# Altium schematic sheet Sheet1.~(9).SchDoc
size A3
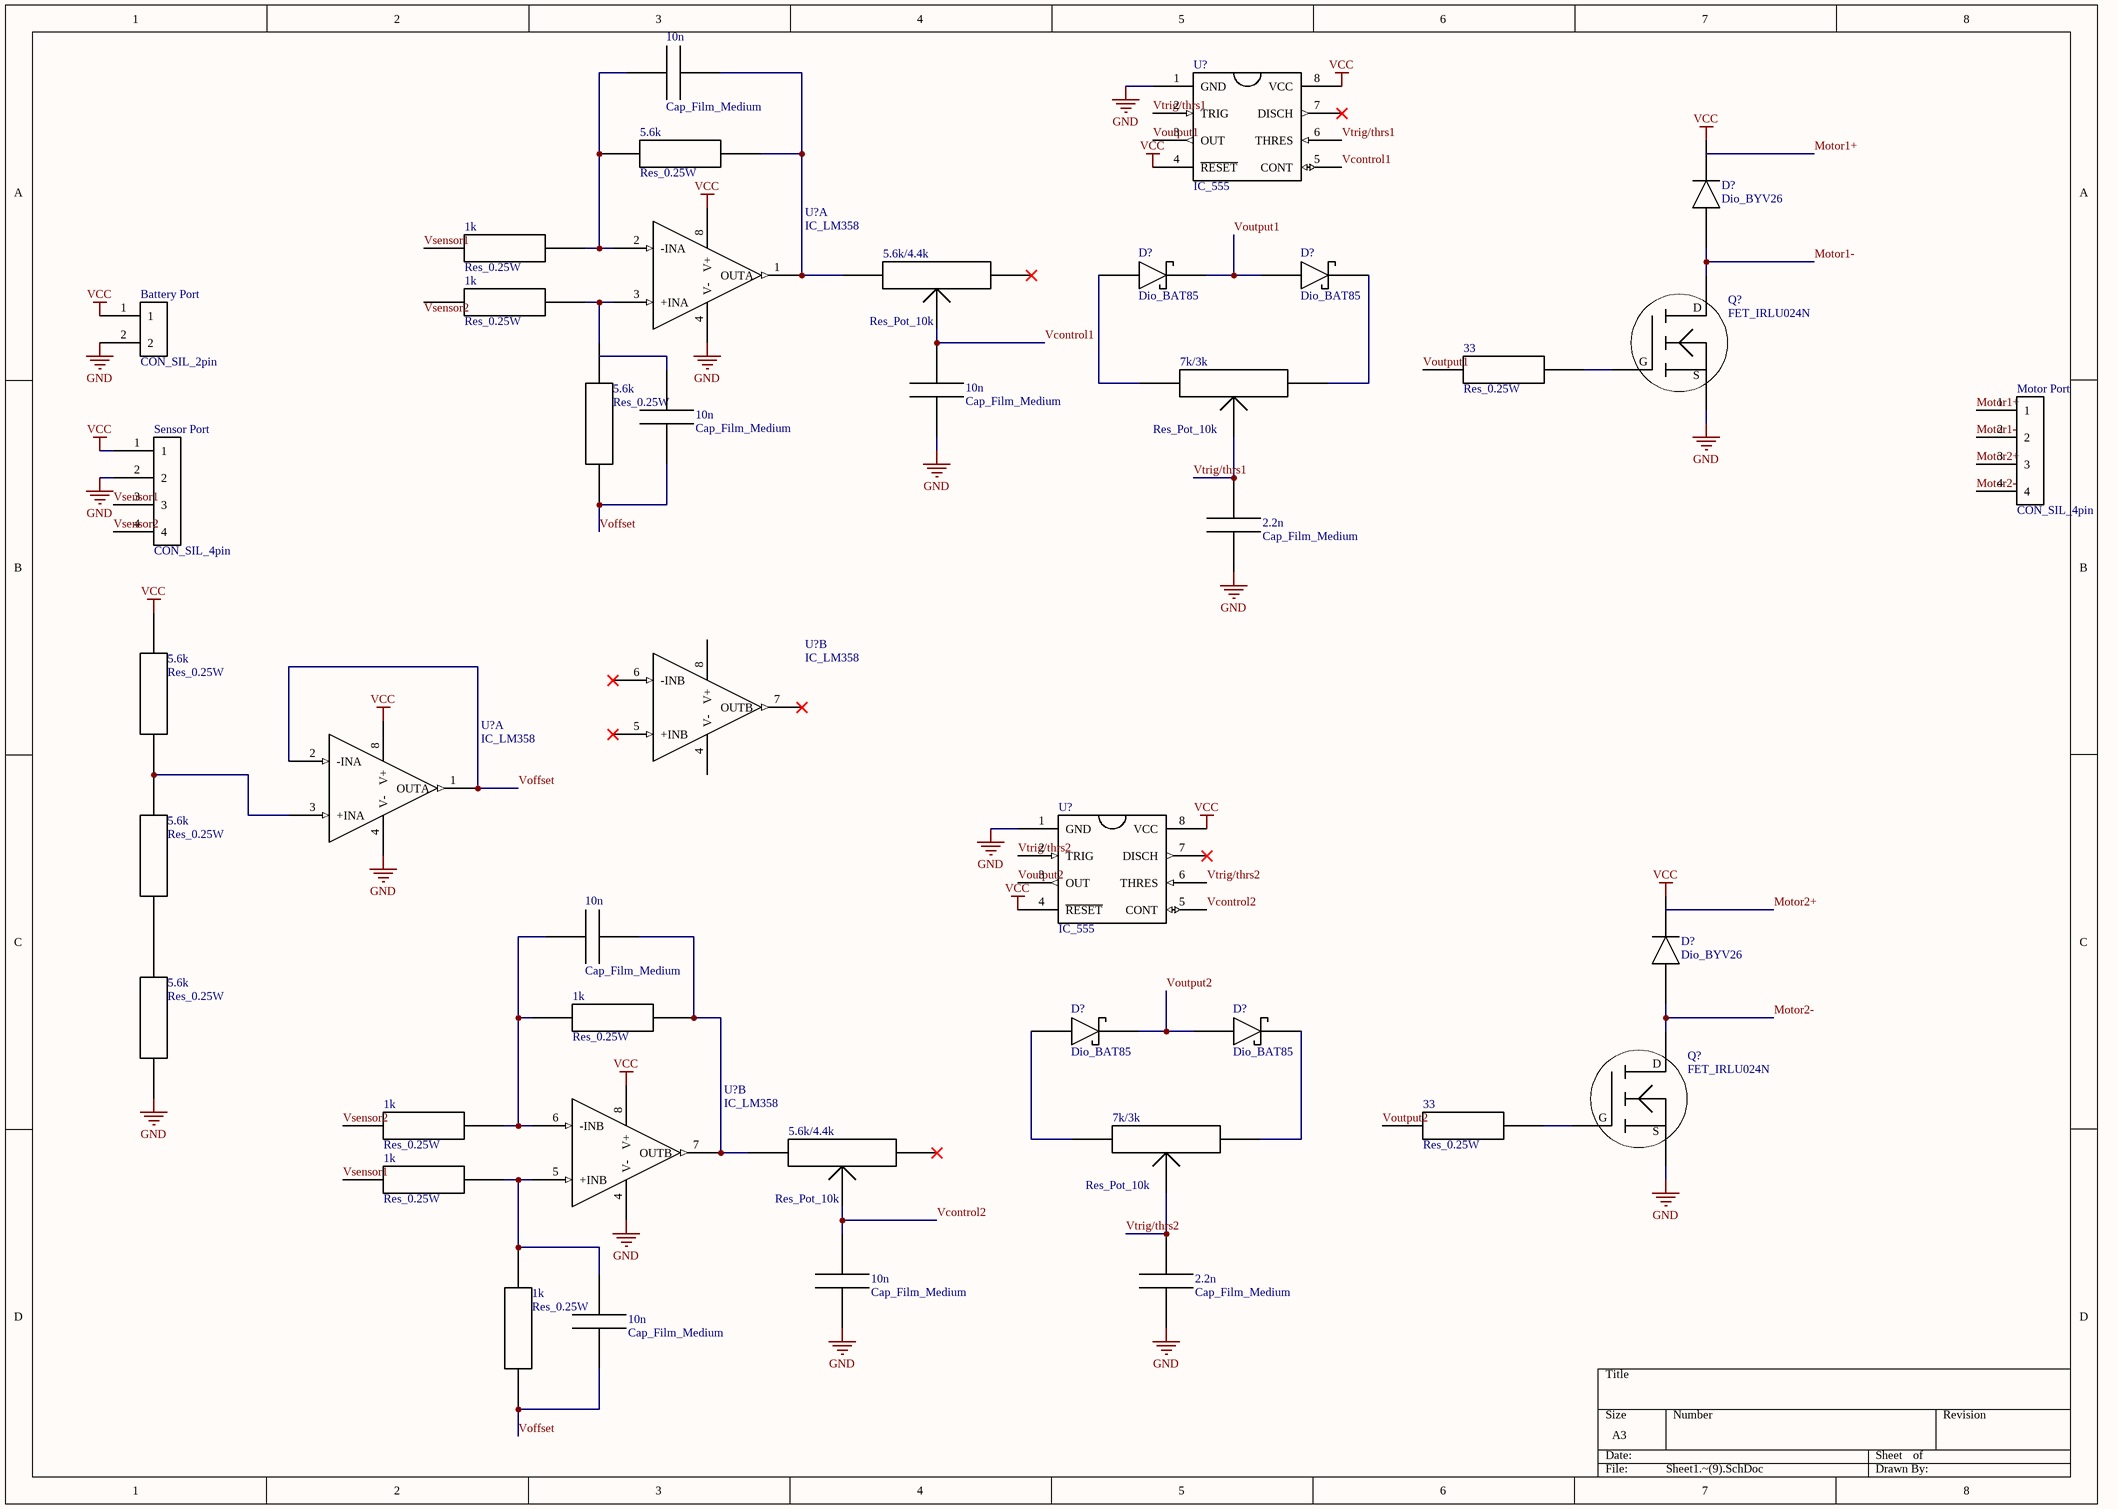
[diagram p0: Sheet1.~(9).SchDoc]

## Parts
(Parts that share a designator on the sheet are numbered #1, #2 ... from top to bottom, then left to right.)
1k#1  Res_0.25W  [Resistor_400mil_pitch]
1k#2  Res_0.25W  [Resistor_400mil_pitch]
1k#3  Res_0.25W  [Resistor_400mil_pitch]
1k#4  Res_0.25W  [Resistor_400mil_pitch]
1k#5  Res_0.25W  [Resistor_400mil_pitch]
1k#6  Res_0.25W  [Resistor_400mil_pitch]
2.2n#1  Cap_Film_Medium  [CAP_FILM_3.2mm]
2.2n#2  Cap_Film_Medium  [CAP_FILM_3.2mm]
5.6k#1  Res_0.25W  [Resistor_400mil_pitch]
5.6k#2  Res_0.25W  [Resistor_400mil_pitch]
5.6k#3  Res_0.25W  [Resistor_400mil_pitch]
5.6k#4  Res_0.25W  [Resistor_400mil_pitch]
5.6k#5  Res_0.25W  [Resistor_400mil_pitch]
5.6k/4.4k#1  Res_Pot_10k  [POT]
5.6k/4.4k#2  Res_Pot_10k  [POT]
7k/3k#1  Res_Pot_10k  [POT]
7k/3k#2  Res_Pot_10k  [POT]
10n#1  Cap_Film_Medium  [CAP_FILM_3.2mm]
10n#2  Cap_Film_Medium  [CAP_FILM_3.2mm]
10n#3  Cap_Film_Medium  [CAP_FILM_3.2mm]
10n#4  Cap_Film_Medium  [CAP_FILM_3.2mm]
10n#5  Cap_Film_Medium  [CAP_FILM_3.2mm]
10n#6  Cap_Film_Medium  [CAP_FILM_3.2mm]
33#1  Res_0.25W  [Resistor_400mil_pitch]
33#2  Res_0.25W  [Resistor_400mil_pitch]
Battery_Port  CON_SIL_2pin  [ece-HDR1X2]
D?#1  Dio_BYV26  [SOD_47]
D?#2  Dio_BAT85  [Diode_SmallSignal]
D?#3  Dio_BAT85  [Diode_SmallSignal]
D?#4  Dio_BYV26  [SOD_47]
D?#5  Dio_BAT85  [Diode_SmallSignal]
D?#6  Dio_BAT85  [Diode_SmallSignal]
Motor_Port  CON_SIL_4pin  [ece-HDR1X4]
Q?#1  FET_IRLU024N  [TO_251AA]
Q?#2  FET_IRLU024N  [TO_251AA]
Sensor_Port  CON_SIL_4pin  [ece-HDR1X4]
U?#1  IC_555  [DIP_8]
U?#2  IC_LM358  [DIP_8]  (part A of 2)
U?#3  IC_LM358  [DIP_8]  (part B of 2)
U?#4  IC_LM358  [DIP_8]  (part A of 2)
U?#5  IC_555  [DIP_8]
U?#6  IC_LM358  [DIP_8]  (part B of 2)

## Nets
GND: 2.2n#1.2 2.2n#2.2 5.6k#5.2 10n#2.2 10n#5.2 Battery_Port.2 Q?#1.3(S) Q?#2.3(S) Sensor_Port.2 U?#1.1(GND) U?#2.4(V-) U?#4.4(V-) U?#5.1(GND) U?#6.4(V-)
VCC: 5.6k#3.1 Battery_Port.1 D?#1.2 D?#4.2 Sensor_Port.1 U?#1.4(~{RESET}) U?#1.8(VCC) U?#2.8(V+) U?#4.8(V+) U?#5.4(~{RESET}) U?#5.8(VCC) U?#6.8(V+)
Motor1+: Motor_Port.1
Motor1-: D?#1.1 Motor_Port.2 Q?#1.1(D)
Motor2+: Motor_Port.3
Motor2-: D?#4.1 Motor_Port.4 Q?#2.1(D)
Vcontrol1: 5.6k/4.4k#1.2 10n#2.1 U?#1.5(CONT)
Vcontrol2: 5.6k/4.4k#2.2 10n#5.1 U?#5.5(CONT)
Voffset: 1k#6.1 5.6k#2.1 10n#3.1 10n#6.1 U?#4.1(OUTA) U?#4.2(-INA)
Voutput1: 33#1.2 D?#2.2 D?#3.1 U?#1.3(OUT)
Voutput2: 33#2.2 D?#5.2 D?#6.1 U?#5.3(OUT)
Vsensor1: 1k#1.1 1k#5.1 Sensor_Port.3
Vsensor2: 1k#4.1 Sensor_Port.4
Vtrig/thrs1: 2.2n#1.1 7k/3k#1.2 U?#1.2(TRIG) U?#1.6(THRES)
Vtrig/thrs2: 2.2n#2.1 7k/3k#2.2 U?#5.2(TRIG) U?#5.6(THRES)
Net1k#1_2: 1k#1.2 5.6k#1.1 10n#1.1 U?#2.2(-INA)
Net1k#2_2: 1k#2.2 5.6k#2.2 U?#2.3(+INA)
Net1k#3_1: 1k#3.1 1k#4.2 10n#4.2 U?#6.6(-INB)
Net1k#3_2: 1k#3.2 5.6k/4.4k#2.3 10n#4.1 U?#6.7(OUTB)
Net1k#5_2: 1k#5.2 1k#6.2 10n#6.2 U?#6.5(+INB)
Net5.6k#1_2: 5.6k#1.2 5.6k/4.4k#1.3 10n#1.2 U?#2.1(OUTA)
Net5.6k#3_2: 5.6k#3.2 5.6k#4.1 U?#4.3(+INA)
Net5.6k#4_2: 5.6k#4.2 5.6k#5.1
Net7k/3k#1_1: 7k/3k#1.1 D?#3.2
Net7k/3k#1_3: 7k/3k#1.3 D?#2.1
Net7k/3k#2_1: 7k/3k#2.1 D?#6.2
Net7k/3k#2_3: 7k/3k#2.3 D?#5.1
Net33#1_1: 33#1.1 Q?#1.2(G)
Net33#2_1: 33#2.1 Q?#2.2(G)

Not connected (* = marked no-connect by the designer): 1k#2 1; 5.6k/4.4k#1 1*; 5.6k/4.4k#2 1*; 10n#3 2; U?#1 7(DISCH)*; U?#3 4(V-) 5(+INB)* 6(-INB)* 7(OUTB)* 8(V+); U?#5 7(DISCH)*

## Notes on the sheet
- Labels drawn without touching a wire or pin: Vsensor2

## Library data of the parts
2.2n#1 2.2n#2 10n#1-10n#6 = Cap_Film_Medium: Cap_Ceramic
Battery_Port = CON_SIL_2pin: 2 pin in line connector
D?#1 D?#4 = Dio_BYV26: BYV26
Motor_Port Sensor_Port = CON_SIL_4pin: 4 pin in line connector
Q?#1 Q?#2 = FET_IRLU024N: N-Chan MOSFET 55V 17A 65mOhm
U?#1 U?#5 = IC_555: NEC555
U?#2-U?#4 U?#6 = IC_LM358: LM358 - Dual Opamp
